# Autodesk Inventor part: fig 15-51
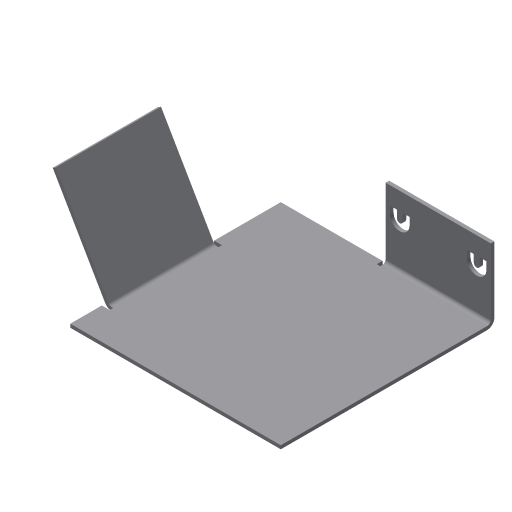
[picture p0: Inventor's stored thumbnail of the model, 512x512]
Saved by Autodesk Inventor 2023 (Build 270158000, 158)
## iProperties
Created: 2002-04
Part Number: fig 15-51
Document SubType Name: Sheet Metal
Density: 1 g/cm^3
Sheet Metal Rule: Default
Material: Generic
Appearance: Default
Control State: 0
Master: False
Checked Out: False
Shininess: 77.0
Angle Display Precision: 2
Document Length Units: 11269
Document Angle Units: 11279
Document Time Units: 11290
Document Mass Units: 11283
Document Length Units Precision: 3
Document Angle Units Precision: 2
Density: 0.0
Volumn: 0.0
Area: 0.0
PropertySet Name: Model Information
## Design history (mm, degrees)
node "Face1"
  sketch "Sketch1"
    geometry: L1 (12.647, 25.882)-(12.647, -14.118); L2 (12.647, -14.118)-(-17.353, -14.118); L3 (-17.353, -14.118)-(-17.353, 15.882); L4 (-17.353, 15.882)-(-2.353, 15.882); L5 (-2.353, 15.882)-(-2.353, 25.882); L6 (-2.353, 25.882)-(12.647, 25.882); 1 further point
    constraints: 12 end point, 4 parallel, 1 perpendicular
    dimensions: "d5" = 30 distance of L2.end L3.end; "d6" = 10 distance of L4.end L5.end; "d7" = 15 distance of L3.end L4.end; "d25" = 15 distance of L5.end L1.start
sketch "Sketch3"
  geometry: L1 (10, -15)-(10, 0)
  constraints: 2 end point
feature "Fold3" sketch "Sketch3" dims "d26" = 0.5 (= BendRadius), "d27" = 90 deg, "d28" = 0.5 (= BendRadius), "d96" = 0.5 (= BendReliefWidth), "d97" = 0.25 (= BendReliefDepth), "d98" = 1 (= MinimumRemnant), "d107" = 0.5 (= Thickness), "SeamGap" = 0.01
node "Flange2"
sketch "Sketch6"
  geometry: L1 (-6.914, 3.413)-(-5.843, 3.413); L2 (-5.843, 0.624)-(-6.914, 0.624); L3 (-6.914, 2.432)-(-5.843, 2.432); L4 (-5.843, 1.605)-(-6.914, 1.605); L5 (-6.914, 0.624)-(-6.914, 1.605); L6 (-6.914, 2.432)-(-6.914, 3.413); L7 (-6.914, 12.568)-(-6.914, 11.587); L8 (-6.914, 14.376)-(-6.914, 13.395); L9 (-6.914, 11.587)-(-5.843, 11.587); L10 (-5.843, 14.376)-(-6.914, 14.376); L11 (-6.914, 12.568)-(-5.843, 12.568); L12 (-5.843, 13.395)-(-6.914, 13.395); A1 r 1.394 centre (-5.843, 2.018) between (-5.843, 0.624) and (-5.843, 3.413); A2 r 0.413 centre (-5.843, 2.018) between (-5.843, 1.605) and (-5.843, 2.432); A3 r 1.394 centre (-5.843, 12.982) between (-5.843, 11.587) and (-5.843, 14.376); A4 r 0.413 centre (-5.843, 12.982) between (-5.843, 12.568) and (-5.843, 13.395)
  constraints: 24 end point, 8 point on circle, 4 centre point, 3 equal length, 1 perpendicular
cut "Cut1" sketch "Sketch6" dims "d49" = 0.5 (= Thickness), "d50" = 0
body "Solid1"
face "Plate1" dims "d107" = 0.5 (= Thickness)
sketch "Sketch5"
  geometry: L1 (20, 0)-(5, 0); L2 (5, 0)-(5, 15); L3 (5, 15)-(20, 15); L4 (20, 15)-(20, 0)
  constraints: 8 end point
face "Plate6" dims "d35" = 10, "d36" = 5, "d38" = 15, "d39" = 60 deg, "d40" = 0.5 (= BendRadius), "d107" = 0.5 (= Thickness), "MinimumRemnant" = 1 (= 2 x Thickness), "BendReliefWidth" = 0.5 (= Thickness)
bend "Bend5" dims "d38" = 15, "d39" = 60 deg, "d40" = 0.5 (= BendRadius), "d99" = 0.5 (= BendReliefWidth), "d100" = 0.25 (= BendReliefDepth), "d101" = 1 (= MinimumRemnant), "d107" = 0.5 (= Thickness), "SeamGap" = 0.01, "MinimumRemnant" = 1 (= 2 x Thickness), "BendReliefWidth" = 0.5 (= Thickness), "TransitionRadius" = 0.5 (= BendRadius)
other parameters: "Thickness" = 0.5, "BendRadius" = 0.5 (= Thickness), "BendReliefDepth" = 0.25 (= 0.5 x Thickness), "CornerReliefSize" = 2 (= 4 x Thickness), "d0" = 0.5 (= BendRadius), "d13" = 0.5 (= BendRadius), "d31" = 0.5 (= BendRadius), "d37" = 0.5 (= BendRadius), "JacobiRadiusSize" = 0.5 (= Thickness), "GapSize" = 0.5 (= Thickness)
